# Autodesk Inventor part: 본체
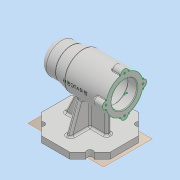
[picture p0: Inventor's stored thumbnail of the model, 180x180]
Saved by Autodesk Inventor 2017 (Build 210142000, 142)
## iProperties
Created: 2019-12
Part Number: 본체
Material: Generic
Document SubType Name: Modeling
Designer: 5-05-le
Density: 1 g/cm^3
Appearance: Default
Author: 5-05-le
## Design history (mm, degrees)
sketch "스케치1"
  geometry: 1 further point
sketch "스케치2"
  geometry: L1 (-45.045, -3.898)-(-45.045, 21.102); L2 (-45.045, 21.102)-(-20.045, 21.102); L3 (-20.045, 21.102)-(-0.045, 26.102); L4 (-0.045, 26.102)-(66.955, 26.102); L5 (66.955, 26.102)-(66.955, -3.898); L6 (66.955, -3.898)-(-45.045, -3.898); 1 further point
  constraints: 12 end point, 3 perpendicular, 1 horizontal, 1 vertical
  dimensions: "d0" = 112 distance between parallel lines of L5 L1; "d1" = 30 distance of L5.end L4.end; "d2" = 25 distance from line of L2.end L1; "d3" = 45 distance from line of L1 L3.end; "d4" = 25 distance of L1.start L1.end
revolve "회전1" sketch "스케치2" stored, may be unused: angle "d5" = 90 deg
sketch "스케치3"
  geometry: L1 (-45.045, -28.898)-(-45.045, 21.102) reference; L2 (-45.045, 21.102)-(-45.045, -3.898); L3 (-45.045, -3.898)-(66.955, -3.898); L4 (66.955, -33.898)-(66.955, 26.102) reference; L5 (66.955, -3.898)-(51.955, -3.898); L6 (51.955, -3.898)-(51.955, 17.102); L7 (51.955, 17.102)-(66.955, 17.102); L8 (66.955, 17.102)-(66.955, -3.898); L9 (51.955, -3.898)-(-2.045, -3.898); L10 (-2.045, -3.898)-(-2.045, 20.102); L11 (-2.045, 20.102)-(51.955, 20.102); L12 (51.955, 20.102)-(51.955, -3.898); L13 (-2.045, -3.898)-(-14.045, -3.898); L14 (-14.045, -3.898)-(-14.045, 17.102); L15 (-14.045, 17.102)-(-2.045, 17.102); L16 (-2.045, 17.102)-(-2.045, -3.898); L17 (-14.045, -3.898)-(-32.045, -3.898); L18 (-32.045, -3.898)-(-32.045, 13.602); L19 (-32.045, 13.602)-(-14.045, 13.602); L20 (-14.045, 13.602)-(-14.045, -3.898); L21 (-32.045, -3.898)-(-36.045, -3.898); L22 (-36.045, -3.898)-(-36.045, 12.102); L23 (-36.045, 12.102)-(-32.045, 12.102); L24 (-32.045, 12.102)-(-32.045, -3.898); L25 (-36.045, -3.898)-(-39.045, -3.898); L26 (-39.045, -3.898)-(-39.045, 6.602); L27 (-39.045, 6.602)-(-36.045, 6.602); L28 (-36.045, 6.602)-(-36.045, -3.898); 1 further point
  constraints: 52 end point, 12 parallel, 6 horizontal, 6 perpendicular, 2 midpoint
  dimensions: "d6" = 25 distance of L1.end L2.end (derived); "d7" = 15 distance of L6.end L7.end; "d8" = 21 distance of L5.end L6.end; "d9" = 54 distance of L10.end L11.end; "d10" = 24 distance of L9.end L10.end; "d11" = 12 distance of L14.end L15.end; "d12" = 21 distance of L13.end L14.end; "d13" = 18 distance of L18.end L19.end; "d14" = 17.5 distance of L17.end L18.end; "d15" = 4 distance of L22.end L23.end; "d16" = 16 distance of L21.end L22.end; "d17" = 3 distance of L26.end L27.end; "d18" = 10.5 distance of L25.end L26.end
revolve "회전2" sketch "스케치3" stored, may be unused: angle "d19" = 90 deg
fillet "모깎기1" dims "d20" = 3
fillet "모깎기2" dims "d21" = 0.3
chamfer "모따기1" distance "d22" = 1; stored, may be unused: second distance "d23" = 2, angle "d24" = 45 deg
sketch "스케치4"
  geometry: L1 (0, 0)-(-30, 0); C1 r 22 at (0, 0) reference; C2 r 6 at (-30, 0); 3 further points
  constraints: 2 coincident, 2 end point, 1 centre point, 1 horizontal, 1 horizontal alignment, 1 other
  dimensions: "d25" = 12 diameter of C2
extrude "돌출1" join sketch "스케치4" distance "d26" = 16; taper "d27" = 0 deg
sketch "스케치5"
  geometry: A1 r 6 centre (0, 0) between (0.6, 5.97) and (0.6, -5.97) reference; 2 further points
  constraints: 1 coincident
hole "구멍1" sketch "스케치5" at (0, 0) diameter "d28" = 3.242; stored, may be unused: countersink angle "d32" = 90 deg, drill point angle "d34" = 118 deg; dims "d29" = 8, "d30" = 4, "d31" = 2, "d33" = 11
fillet "모깎기3" dims "d35" = 3
fillet "모깎기4" dims "d36" = 1
fillet "모깎기5" dims "d40" = 3
fillet "모깎기6" dims "d41" = 1
fillet "모깎기7" dims "d42" = 3
fillet "모깎기8" dims "d43" = 10
node "작업 평면1"
sketch "스케치6"
  geometry: L1 (66.955, -2.277)-(66.955, -5.519) reference; L2 (66.955, -3.898)-(66.955, 32.102); L3 (66.955, 32.102)-(53.955, 32.102) reference; L4 (66.955, -3.898)-(10.955, -3.898); L5 (66.955, -27.094)-(34.151, -59.898); L6 (34.151, -59.898)-(-12.241, -59.898); L7 (-12.241, -59.898)-(-45.045, -27.094); L8 (-45.045, -27.094)-(-45.045, 19.298); L9 (-45.045, 19.298)-(-12.241, 52.102); L10 (-12.241, 52.102)-(34.151, 52.102); L11 (34.151, 52.102)-(66.955, 19.298); L12 (66.955, 19.298)-(66.955, -27.094); 2 further points
  constraints: 20 end point, 2 midpoint, 1 coincident, 1 horizontal, 1 point on line, 1 vertical, 17 other
  dimensions: "d45" = 56 distance of L2.start L4.end
extrude "돌출2" join sketch "스케치6" distance "d46" = 10; taper "d47" = 0 deg
sketch "스케치7"
  geometry: L1 (66.955, 19.298)-(34.151, 52.102) reference; L2 (-12.241, 52.102)-(-45.045, 19.298) reference; L3 (-45.045, -27.094)-(-12.241, -59.898) reference; L4 (34.151, -59.898)-(66.955, -27.094) reference; L5 (66.955, -27.094)-(66.955, 19.298) reference; L6 (66.955, -3.898)-(10.955, -3.898); L7 (10.955, -3.898)-(50.553, 35.7); L8 (66.955, 19.298)-(34.151, 52.102) reference; L9 (10.955, -3.898)-(-28.643, 35.7); L10 (10.955, -3.898)-(-28.643, -43.496); L11 (10.955, -3.898)-(50.553, -43.496); C1 r 5 at (50.553, 35.7); C2 r 5 at (-28.643, 35.7); C3 r 5 at (-28.643, -43.496); C4 r 5 at (50.553, -43.496); 1 further point
  constraints: 10 end point, 5 midpoint, 4 centre point, 4 coincident, 1 horizontal, 1 perpendicular
  dimensions: "d48" = 56 distance of L6.start L6.end; "d49" = 10 diameter of C1; "d50" = 10 diameter of C2; "d51" = 10 diameter of C3; "d52" = 10 diameter of C4
extrude "돌출3" cut sketch "스케치7" distance "d53" = 10; taper "d54" = 0 deg
sketch "스케치8"
  geometry: L1 (34.151, 52.102)-(-12.241, 52.102) reference; L2 (-45.045, 19.298)-(-45.045, -27.094) reference; L3 (-12.241, -59.898)-(34.151, -59.898) reference; L4 (66.955, -27.094)-(66.955, 19.298) reference; L5 (66.955, -3.898)-(41.955, -3.898); L6 (-45.045, -3.898)-(-27.045, -3.898); L7 (10.955, 52.102)-(10.955, 32.102); L8 (10.955, -59.898)-(10.955, -39.898); L9 (10.955, -39.898)-(6.955, -39.898); L10 (6.955, 32.102)-(14.955, 32.102); L11 (14.955, -39.898)-(10.955, -39.898); L12 (41.955, -3.898)-(41.955, 0.102); L13 (-27.045, -3.898)-(-27.045, 0.102); L14 (-27.045, -3.898)-(-27.045, -7.898); L15 (41.955, -7.898)-(41.955, -3.898); L16 (14.955, 32.102)-(14.955, 0.102); L17 (14.955, -7.898)-(14.955, -39.898); L18 (41.955, 0.102)-(14.955, 0.102); L19 (6.955, 0.102)-(-30.045, 0.102); L20 (-27.045, -7.898)-(6.955, -7.898); L21 (14.955, -7.898)-(41.955, -7.898); L22 (6.955, -39.898)-(6.955, -7.898); L23 (6.955, 0.102)-(6.955, 32.102); L24 (6.955, -7.898)-(14.955, -7.898); L25 (6.955, 0.102)-(14.955, 0.102); 1 further point
  constraints: 42 end point, 14 perpendicular, 4 horizontal, 4 midpoint, 3 vertical, 2 point on line, 1 parallel
  dimensions: "d55" = 25 distance of L5.start L5.end; "d56" = 18 distance of L6.start L6.end; "d57" = 20 distance of L7.start L7.end; "d58" = 20 distance of L8.start L8.end; "d59" = 4 distance of L8.end L9.end; "d60" = 8 distance of L10.start L10.end; "d61" = 4 distance of L5.end L12.end; "d62" = 4 distance of L6.end L14.end
extrude "돌출4" join sketch "스케치8" stored distance "d63" = 10; taper "d64" = 0 deg
feature "면 기울기1" dims angle "d65" = 25 deg
sketch "스케치9"
  geometry: 1 further point
node "작업 평면3"
  node "작업 평면2"
sketch "스케치10"
  geometry: 1 further point
sketch "스케치11"
  geometry: L1 (-59.898, -80)-(-59.898, -70) reference; L2 (-47.031, -70)-(-59.898, -70) reference; L3 (-39.96, -80)-(-39.96, -70) reference; L4 (-7.898, -70)-(0.102, -70) reference; A1 r 29.91 centre (-3.898, 0) between (0.102, -29.642) and (-7.898, -29.642) reference; 1 further point
feature "리브1" sketch "스케치11" dims "d70" = 1, "d71" = 8, "d72" = 0, "d73" = 0, "d74" = 1, "d75" = 1
sketch "스케치12"
  geometry: L1 (52.102, -80)-(52.102, -70) reference; L2 (52.102, -70)-(32.102, -70); L3 (30.7, -70)-(39.236, -70) reference; L4 (32.165, -70)-(14.737, -22.117); L5 (0, -70)-(32.165, -70); 1 further point
  constraints: 6 end point, 1 horizontal, 1 point on line
  dimensions: "d76" = 20 distance of L1.end L2.end; "d77" = 110 deg angle of L4 L2
feature "리브2" sketch "스케치12" dims "d78" = 1, "d79" = 8, "d80" = 0, "d81" = 0, "d82" = 1, "d83" = 1
fillet "모깎기9" dims "d84" = 3
fillet "모깎기10" dims "d85" = 3
sketch "스케치13"
  geometry: 1 further point
sketch "스케치14"
  geometry: C1 r 1.621 at (30, 30) reference; C2 r 1.621 at (60, 0) reference; C3 r 1.621 at (30, -30) reference; C4 r 22 at (30, 0) reference; C5 r 1.621 at (0, 0) reference; A1 r 30 centre (30, 0) between (23.229, 29.226) and (0.774, 6.771) reference; A2 r 1 centre (-0.2, 6.997) between (-0.171, 5.998) and (0.774, 6.771) reference; A3 r 6 centre (0, 0) between (-0.171, 5.998) and (-0.171, -5.998) reference; A4 r 1 centre (-0.2, -6.997) between (0.774, -6.771) and (-0.171, -5.998) reference; A5 r 30 centre (30, 0) between (0.774, -6.771) and (23.229, -29.226) reference; A6 r 1 centre (23.003, -30.2) between (24.002, -30.171) and (23.229, -29.226) reference; A7 r 6 centre (30, -30) between (24.002, -30.171) and (35.998, -30.171) reference; A8 r 1 centre (36.997, -30.2) between (36.771, -29.226) and (35.998, -30.171) reference; A9 r 30 centre (30, 0) between (36.771, -29.226) and (59.226, -6.771) reference; A10 r 1 centre (60.2, -6.997) between (60.171, -5.998) and (59.226, -6.771) reference; A11 r 6 centre (60, 0) between (60.171, -5.998) and (60.171, 5.998) reference; A12 r 1 centre (60.2, 6.997) between (59.226, 6.771) and (60.171, 5.998) reference; A13 r 30 centre (30, 0) between (59.226, 6.771) and (36.771, 29.226) reference; A14 r 1 centre (36.997, 30.2) between (35.998, 30.171) and (36.771, 29.226) reference; A15 r 6 centre (30, 30) between (35.998, 30.171) and (24.002, 30.171) reference; A16 r 1 centre (23.003, 30.2) between (23.229, 29.226) and (24.002, 30.171) reference; 1 further point
node "작업 평면4"
node "작업 평면5"
node "작업 평면6"
fillet "모깎기11" dims "d87" = 3
fillet "모깎기12" dims "d88" = 3
node "작업 평면7"
sketch "스케치15"
  geometry: 2 further points
  constraints: 1 other
node "솔리드1"
pattern_circular "원형 패턴1" dims angle "d38" = 360 deg
mirror "미러1"
other parameters: "d66" = 67, "d67" = -56, "d86" = -3.898
